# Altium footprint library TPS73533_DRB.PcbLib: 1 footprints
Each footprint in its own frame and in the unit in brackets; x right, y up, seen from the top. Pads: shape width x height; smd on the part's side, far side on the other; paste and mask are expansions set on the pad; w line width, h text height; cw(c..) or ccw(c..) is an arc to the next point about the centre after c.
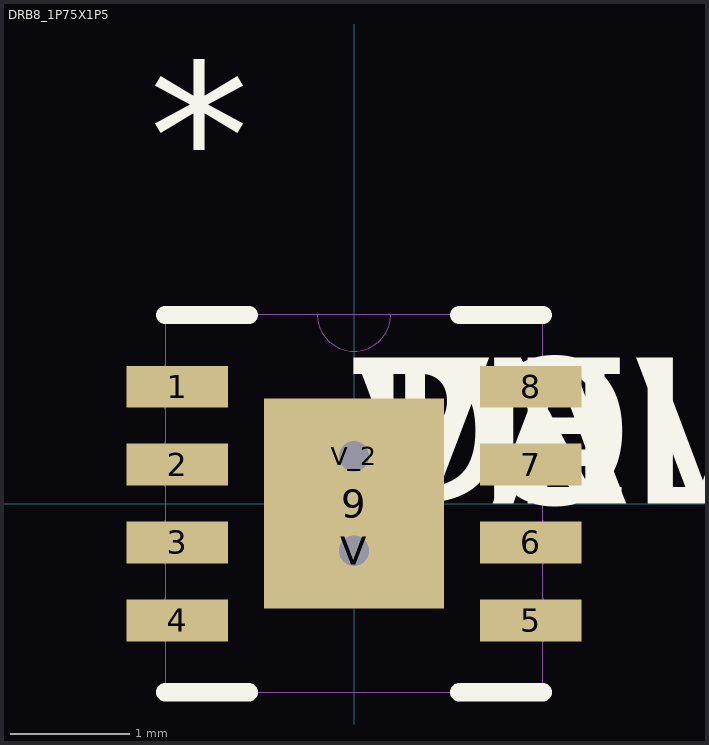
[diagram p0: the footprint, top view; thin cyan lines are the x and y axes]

## DRB8_1P75X1P5 [mm]
pads (11):
  rect 0.85x0.35 smd paste-0.412: 1(-1.475,0.975) 2(-1.475,0.325) 3(-1.475,-0.325) 4(-1.475,-0.975) 5(1.475,-0.975) 6(1.475,-0.325) 7(1.475,0.325) 8(1.475,0.975)
  rect 1.5x1.75 smd paste-0.862 mask-0.864: 9(0,0)
  round 0.508 / inner round 1.524 / far side round 0.508 hole 0.254: V(0,-0.394) V_2(0,0.394)
Layer0:
  region: 0,0.875
  region: 0,-0.875
  region: -0.317,0.875 -0.547,0.875 -0.547,1.575 -0.317,1.575
  region: 0.317,0.875 0.547,0.875 0.547,1.575 0.317,1.575
  region: 0.317,-0.875 0.547,-0.875 0.547,-1.575 0.317,-1.575
  region: -0.317,-0.875 -0.547,-0.875 -0.547,-1.575 -0.317,-1.575
Top Overlay:
  lines w0.152: -1.575,-1.575 -0.88,-1.575 ; -1.575,1.575 -0.88,1.575 ; 0.88,-1.575 1.575,-1.575 ; 0.88,1.575 1.575,1.575
  text "*" at -1.709,2.468 h1.27
  text "PN" at 0,0 h1.27
  text "DEV" at 0,0 h1.27
  text "VAL" at 0,0 h1.27
  text "TOL" at 0,0 h1.27
Top Paste:
  region: -1.075,1.125 -1.875,1.125 -1.875,0.825 -1.075,0.825
  region: -1.075,0.475 -1.875,0.475 -1.875,0.175 -1.075,0.175
  region: -1.075,-0.175 -1.875,-0.175 -1.875,-0.475 -1.075,-0.475
  region: -1.075,-0.825 -1.875,-0.825 -1.875,-1.125 -1.075,-1.125
  region: 1.875,-0.825 1.075,-0.825 1.075,-1.125 1.875,-1.125
  region: 1.875,-0.175 1.075,-0.175 1.075,-0.475 1.875,-0.475
  region: 1.875,0.475 1.075,0.475 1.075,0.175 1.875,0.175
  region: 1.875,1.125 1.075,1.125 1.075,0.825 1.875,0.825
  region: 0,0.875
  region: 0,-0.875
  region: -0.368,0.926 -0.496,0.926 -0.496,1.524 -0.368,1.524
  region: 0.368,0.926 0.496,0.926 0.496,1.524 0.368,1.524
  region: 0.368,-0.926 0.496,-0.926 0.496,-1.524 0.368,-1.524
  region: -0.368,-0.926 -0.496,-0.926 -0.496,-1.524 -0.368,-1.524
  region: -0.1,0.8 -0.675,0.8 -0.675,0.494 -0.241,0.494 -0.1,0.635
  region: -0.241,0.294 -0.675,0.294 -0.675,-0.294 -0.241,-0.294 -0.1,-0.152 -0.1,0.152
  region: -0.241,-0.494 -0.675,-0.494 -0.675,-0.8 -0.1,-0.8 -0.1,-0.635
  region: 0.675,0.8 0.1,0.8 0.1,0.635 0.241,0.494 0.675,0.494
  region: 0.675,0.294 0.241,0.294 0.1,0.152 0.1,-0.152 0.241,-0.294 0.675,-0.294
  region: 0.675,-0.494 0.241,-0.494 0.1,-0.635 0.1,-0.8 0.675,-0.8
Top Solder:
  region: -0.98,1.22 -1.97,1.22 -1.97,0.73 -0.98,0.73
  region: -0.98,0.57 -1.97,0.57 -1.97,0.08 -0.98,0.08
  region: -0.98,-0.08 -1.97,-0.08 -1.97,-0.57 -0.98,-0.57
  region: -0.98,-0.73 -1.97,-0.73 -1.97,-1.22 -0.98,-1.22
  region: 1.97,-0.73 0.98,-0.73 0.98,-1.22 1.97,-1.22
  region: 1.97,-0.08 0.98,-0.08 0.98,-0.57 1.97,-0.57
  region: 1.97,0.57 0.98,0.57 0.98,0.08 1.97,0.08
  region: 1.97,1.22 0.98,1.22 0.98,0.73 1.97,0.73
  region: 0,0.875
  region: 0,-0.875
  region: -0.317,0.875 -0.547,0.875 -0.547,1.575 -0.317,1.575
  region: 0.317,0.875 0.547,0.875 0.547,1.575 0.317,1.575
  region: 0.317,-0.875 0.547,-0.875 0.547,-1.575 0.317,-1.575
  region: -0.317,-0.875 -0.547,-0.875 -0.547,-1.575 -0.317,-1.575
  region: -0.814,0.594 -0.814,0.938 0.814,0.938 0.814,0.594
  region: -0.814,-0.194 -0.814,0.194 0.814,0.194 0.814,-0.194
  region: -0.814,-0.938 -0.814,-0.594 0.814,-0.594 0.814,-0.938
  region: -0.814,-0.938 -0.814,0.938 -0.2,0.938 -0.2,-0.938
  region: 0.2,-0.938 0.2,0.938 0.814,0.938 0.814,-0.938
Mechanical 1:
  lines w0: -0.305,1.575 ccw(c0,1.575) 0.305,1.575 ; -1.575,-1.16 -1.575,-0.79 ; -1.575,-1.16 -1.575,-0.79 ; -1.575,-1.16 -1.575,-1.16 ; -1.575,-0.79 -1.575,-0.79 ; -1.575,-0.51 -1.575,-0.14 ; -1.575,-0.51 -1.575,-0.14 ; -1.575,-0.51 -1.575,-0.51 ; -1.575,-0.14 -1.575,-0.14 ; -1.575,0.14 -1.575,0.51 ; -1.575,0.14 -1.575,0.51 ; -1.575,0.14 -1.575,0.14 ; -1.575,0.51 -1.575,0.51 ; -1.575,0.79 -1.575,1.16 ; -1.575,0.79 -1.575,1.16 ; -1.575,0.79 -1.575,0.79 ; -1.575,1.16 -1.575,1.16 ; 1.575,-1.16 1.575,-0.79 ; 1.575,-1.16 1.575,-1.16 ; 1.575,-1.16 1.575,-0.79 ; 1.575,-0.79 1.575,-0.79 ; 1.575,-0.51 1.575,-0.14 ; 1.575,-0.51 1.575,-0.51 ; 1.575,-0.51 1.575,-0.14 ; 1.575,-0.14 1.575,-0.14 ; 1.575,0.14 1.575,0.51 ; 1.575,0.14 1.575,0.14 ; 1.575,0.14 1.575,0.51 ; 1.575,0.51 1.575,0.51 ; 1.575,0.79 1.575,1.16 ; 1.575,0.79 1.575,0.79 ; 1.575,0.79 1.575,1.16 ; 1.575,1.16 1.575,1.16 ; -1.575,-1.575 1.575,-1.575 1.575,1.575 -1.575,1.575 -1.575,-1.575
  text "*" at -1.709,2.468 h1.27
  text "RefDes2" at 0,0 h1.27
